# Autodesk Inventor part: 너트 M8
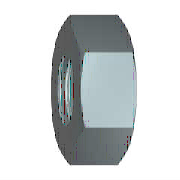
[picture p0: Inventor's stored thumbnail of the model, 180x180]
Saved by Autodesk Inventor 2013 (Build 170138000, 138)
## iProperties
IsCustomPart: 1
Created: 2012-02
Part Number: 너트 M8
Material: 강철, 연강
Description: 6각 너트 및 6각 가는 너트
Document SubType Name: Modeling
Standard: KS B 1012
Designer: mduedu
Standards Organization: KS
Language: ko-KR
Size Designation: M 8
Categories: <MemberInstance><Categories><Category DisplayName="조임쇠" InternalName="e4da775c-781d-43d5-af7c-5136215cf5a6" Mnemonic="FSTN"><Category DisplayName="너트" InternalN
Density: 7.86 g/cm^3
Mass: 4.30432 g
Surface Area: 5.27675 cm^2
Volume: 0.547623 cm^3
Author: mduedu
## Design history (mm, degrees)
sketch "스케치1"
  geometry: L1 (-7.506, 0)-(-3.753, 6.5); L2 (-3.753, 6.5)-(3.753, 6.5); L3 (3.753, 6.5)-(7.506, 0); L4 (7.506, 0)-(3.753, -6.5); L5 (3.753, -6.5)-(-3.753, -6.5); L6 (-3.753, -6.5)-(-7.506, 0); 2 further points
  constraints: 12 end point, 1 coincident, 1 horizontal, 11 other
  dimensions: "d0" = 15.01111 distance of L3.end L1.start (= 1.1547 x SW)
extrude "본체" new body sketch "스케치1" distance "d1" = 5 (= KOH); taper "d2" = 0 deg
sketch "스케치2"
  geometry: L1 (0, 3.753)-(0, 7.506) reference; L2 (0, 7.506)-(5, 7.506) reference; L3 (5, 3.753)-(5, 7.506) reference; L4 (-1, 0)-(6, 0) reference; L5 (0.581, 7.506)-(0, 6.5); L6 (4.419, 7.506)-(5, 6.5)
  constraints: 4 end point, 4 point on line
  dimensions: "d3" = 30 deg angle of L1 L5 (= ANG1); "d4" = 30 deg angle of L3 L6 (= ANG2); "d5" = 13 diameter of L5.end L4 (= SW0); "d6" = 13 diameter of L6.end L4 (= SW01)
revolve "모따기1" sketch "스케치2" stored, may be unused: angle "d7" = 90 deg
sketch "스케치3"
  geometry: A1 r 6.5 centre (0, 0) between (-3.25, -5.629) and (3.25, -5.629) reference; 1 further point
  constraints: 1 coincident
hole "스레드" sketch "스케치3" at (0, 0) diameter "d25" = 6.647; stored, may be unused: countersink angle "d29" = 82 deg, drill point angle "d31" = 118 deg; dims "d26" = 6, "d27" = 4, "d28" = 2, "d30" = 8
workaxis "Work Axis1"
workplane "Work Plane1"
body "Solid1"
chamfer "모따기2" distance "d8" = 0.67658 (= -0.5 x GD1 + 0.5 x NND); stored, may be unused: angle "d9" = 30 deg, second distance "d40" = 0.67658 (= -0.5 x GD1 + 0.5 x NND)
chamfer "모따기3" distance "d10" = 0.67658 (= -0.5 x GD1 + 0.5 x NND); stored, may be unused: angle "d11" = 30 deg, second distance "d41" = 0.67658 (= -0.5 x GD1 + 0.5 x NND)
other parameters: "ANG1" = 30 deg [user parameter; used in 1 equation term], "ANG2" = 30 deg [user parameter; used in 1 equation term], "NND" = 8 [user parameter; used in 4 equation terms], "KOH" = 5 [user parameter; used in 1 equation term], "SW" = 13 [user parameter; used in 4 equation terms], "SW0" = 13 (= SW) [user parameter; used in 1 equation term], "SW01" = 13 (= SW) [user parameter; used in 1 equation term], "GD1" = 6.64684 (computed from THREADDIA, PTC, TOA) [user parameter; used in 4 equation terms], "d13" = 0, "d14" = 0, "d39" = 0, "d42" = 0, "GUL" = 0.67658 (= 0.541266 x PTC) [user parameter], "TPU" = 8 (computed from PTC) [user parameter], "THREADDIA" = 8 [user parameter; used in 1 equation term], "TOA" = 30 deg [user parameter; used in 1 equation term], "PTC" = 1.25 [user parameter; used in 4 equation terms], "E0" = 15.015 (= 1.155 x SW) [user parameter], "GAL" = 0.67658 (= 0.541266 x PTC) [user parameter]
